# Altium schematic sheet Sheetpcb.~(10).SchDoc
size A; SheetNumber: 2; SheetTotal: 2
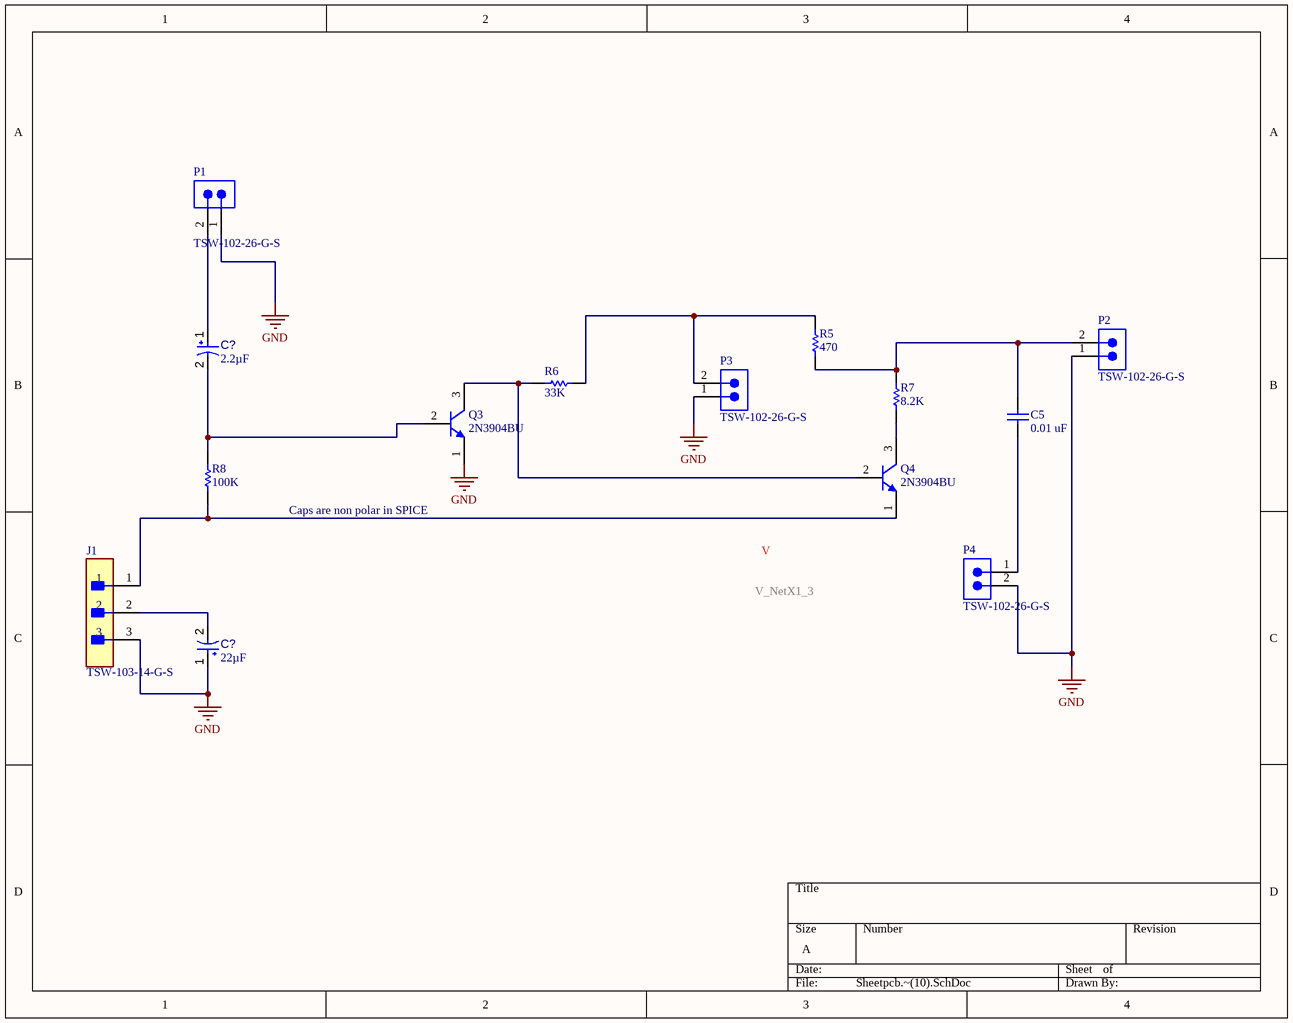
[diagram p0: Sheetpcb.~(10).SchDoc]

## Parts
(Parts that share a designator on the sheet are numbered #1, #2 ... from top to bottom, then left to right.)
C5  value 0.01 uF  (hidden comment: Capacitor)
C?#1  value 2.2µF  [CAPPR55-200-1100X500X1200]  (hidden comment: ECA1HM2R2)
C?#2  value 22µF  [CAPPR55-200-1100X500X1200]  (hidden comment: ECA1HM220)
J1  TSW-103-14-G-S  [FP-TSW-103-14-G-S-MFG]
P1  TSW-102-26-G-S  [SMTC-TSW-102-26-XX-S]
P2  TSW-102-26-G-S  [SMTC-TSW-102-26-XX-S]
P3  TSW-102-26-G-S  [SMTC-TSW-102-26-XX-S]
P4  TSW-102-26-G-S  [SMTC-TSW-102-26-XX-S]
Q3  2N3904BU  [FAIR-TO-92]
Q4  2N3904BU  [FAIR-TO-92]
R5  value 470  (hidden comment: Resistor)
R6  value 33K  (hidden comment: Resistor)
R7  value 8.2K  (hidden comment: Resistor)
R8  value 100K  (hidden comment: Resistor)

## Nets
GND: C?#2.1 J1.3 P1.1 P2.1 P3.1 P4.2 Q3.1(E)
NetC5_1: C5.1 P4.1
NetC5_2: C5.2 P2.2 R5.1 R7.1
NetC?#1_1: C?#1.1 P1.2
NetC?#1_2: C?#1.2 Q3.2(B) R8.2
NetC?#2_2: C?#2.2 J1.2
NetJ1_1: J1.1 Q4.1(E) R8.1
NetP3_2: P3.2 R5.2 R6.1
NetQ3_3: Q3.3(C) Q4.2(B) R6.2
NetQ4_3: Q4.3(C) R7.2

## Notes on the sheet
- Caps are non polar in SPICE

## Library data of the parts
C5 = Capacitor: SimulationGenericComponent: True
C?#1 = CMP-001-00029-7: Aluminum Electrolytic Capacitor, 2.2 uF, +/- 20%, 50 V, -40 to 85 degC, 2-Pin THD, RoHS, Bulk; Manufacturer: Panasonic; Voltage Rating: 50V; Ripple Current: 20mA
C?#2 = CMP-001-00027-7: Aluminum Electrolytic Capacitor, 22 uF, +/- 20%, 50 V, -40 to 85 degC, 2-Pin THD, RoHS, Bulk; Manufacturer: Panasonic; Ripple Current (AC): 100mA; Voltage Rating: 50V
J1 = CMP-02766-001743-1: CONN HEADER VERT 3POS 2.54MM; Max Voltage Rating (AC): 550V; Number of Positions: 3; Max Current Rating: 7.6A; Gender: Male
P1-P4 = CMP-1024-00327-1: 0.025" SQ Post Header, Through-hole, Vertical, -55 to 125 degC, 2.54 mm Pitch, 2-Pin, Male, RoHS; Manufacturer: Samtec; Pitch: 2.54 mm
Q3 Q4 = CMP-2000-04944-1: NPN General-Purpose Amplifier, 40 V VCEO, 0.2 A, -55 to 150 degC, 2-Pin TO-92, RoHS, Bulk; Manufacturer: FairchildSemiconductor; Maximum Collector Base Voltage: 60V; Minimum DC Current Gain: 40@0.1mA@1V; Maximum Collector Emitter Voltage: 40V; Maximum DC Collector Current: 0.2A; Rad Hard: No; Maximum Operating Frequency: 300(Min)MHz; Maximum Collector Emitter Saturation Voltage: 0.2@1mA@10mA; Maximum Power Dissipation: 625mW
R5-R8 = Resistor: TC1: 0; SimulationGenericComponent: True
